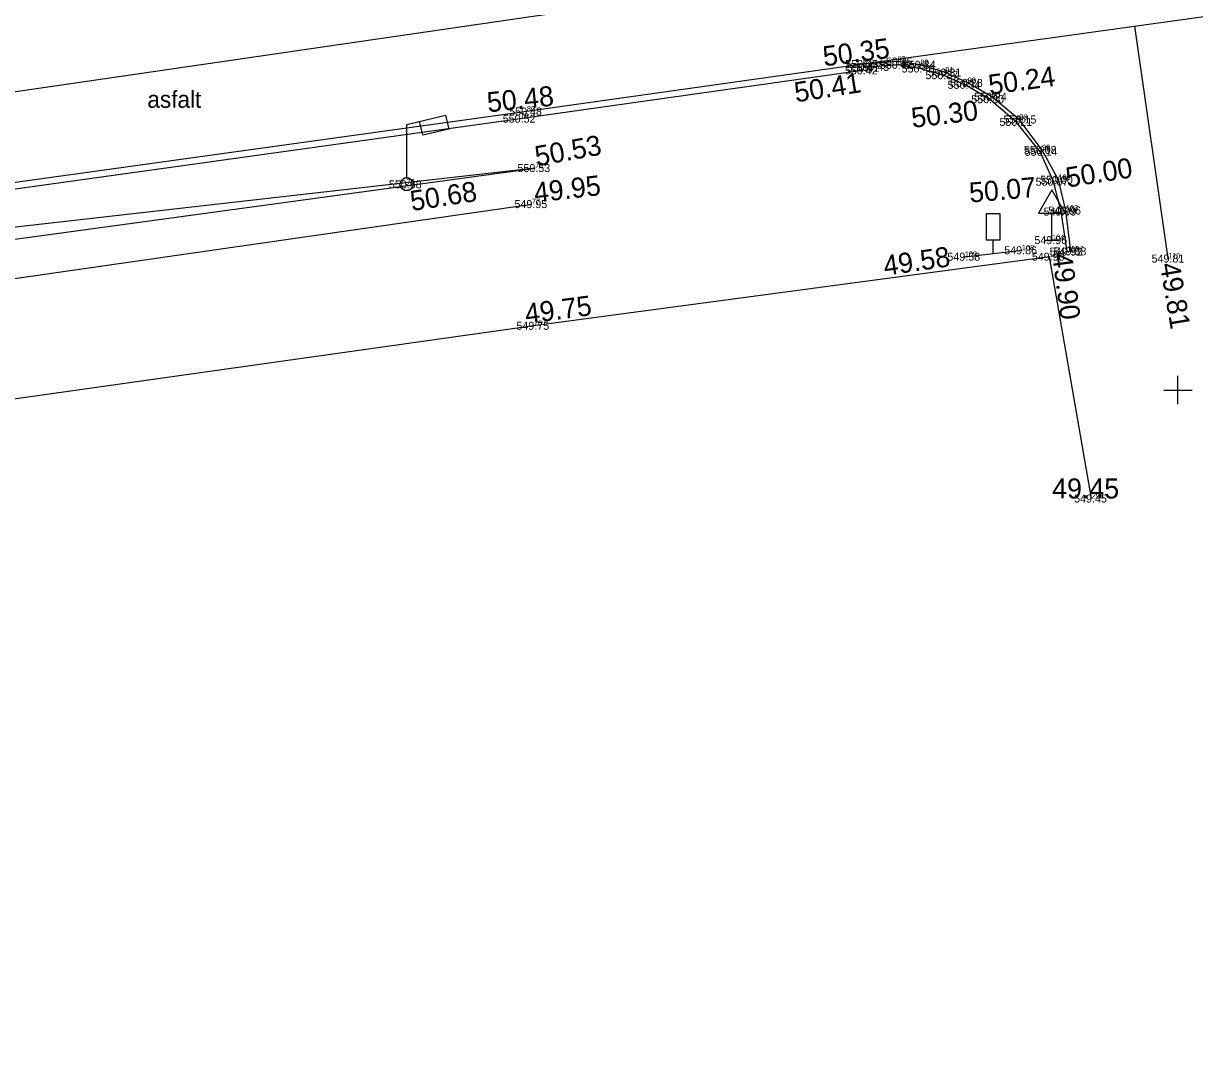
# Model space of a CAD drawing. Extents: x -866693 to -866303, y -1041966 to -1040244.
# Drawn here: x -866593.26 to -866549.38, y -1040325.42 to -1040286.26 of the extents above; entities that cross this region are included whole.
import ezdxf

# ---------------------------------------------------------------- set-up
doc = ezdxf.new("R2010")
doc.units = 0
for name, color, linetype in [('1 hrana zpevněné komunikace-plocha', 7, 'Continuous'), ('10 plot drátěný', 7, 'Continuous'), ('3 osa komunikace', 7, 'Continuous'), ('42 dopravní značka', 7, 'Continuous'), ('43 lampa', 7, 'Continuous'), ('5 obrubník nahoře (chodník)', 7, 'Continuous'), ('7 hrana svah nahoře', 7, 'Continuous'), ('8 hrana svah dole', 7, 'Continuous'), ('82 informační tabule', 7, 'Continuous'), ('Bod', 7, 'Continuous'), ('Nadmořská výška', 7, 'Continuous'), ('Nadmořská výška_tisk', 7, 'Continuous'), ('popisy', 7, 'Continuous'), ('Síť křížek', 7, 'Continuous'), ('Číslo bodu', 7, 'Continuous')]:
    doc.layers.add(name, color=color, linetype=linetype)

msp = doc.modelspace()

# ---------------------------------------------------------------- linework, layer by layer
at = {"layer": '1 hrana zpevněné komunikace-plocha'}
for points in [[(-866503.553, -1040279.722), (-866523.034, -1040282.41), (-866541.374, -1040284.946), (-866561.808, -1040287.782), (-866574.398, -1040289.556), (-866602.398, -1040293.439), (-866619.972, -1040295.863), (-866638.769, -1040298.486), (-866650.196, -1040300.008), (-866657.766, -1040301.183), (-866663.405, -1040303.497), (-866666.7, -1040305.877), (-866670.718, -1040310.555), (-866673.161, -1040315.92), (-866674.075, -1040319.269), (-866673.907, -1040325.701)], [(-866554.01, -1040294.795), (-866554.201, -1040293.268), (-866554.48, -1040292.12), (-866555.095, -1040291.004), (-866555.948, -1040289.861), (-866556.978, -1040289.013), (-866557.879, -1040288.487), (-866558.716, -1040288.097), (-866559.651, -1040287.814), (-866560.506, -1040287.691), (-866561.808, -1040287.782)]]:
    msp.add_lwpolyline(points, dxfattribs=at)
at = {"layer": '10 plot drátěný'}
msp.add_lwpolyline([(-866553.237, -1040304.059), (-866554.808, -1040295.001), (-866574.139, -1040297.591), (-866600.998, -1040301.373), (-866619.297, -1040303.884), (-866638.342, -1040306.448), (-866649.995, -1040308.373)], dxfattribs=at)
at = {"layer": '3 osa komunikace'}
msp.add_line((-866550.37, -1040295.067), (-866551.619, -1040286.368), dxfattribs=at)
msp.add_lwpolyline([(-866675.016, -1040299.403), (-866658.944, -1040297.823), (-866639.253, -1040295.089), (-866620.168, -1040292.742), (-866603.167, -1040290.212), (-866574.251, -1040285.999), (-866539.891, -1040281.121), (-866503.725, -1040276.174)], dxfattribs=at)
at = {"layer": '42 dopravní značka'}
for points in [[(-866554.721, -1040294.375), (-866554.721, -1040293.375), (-866554.221, -1040293.375), (-866554.721, -1040292.5), (-866555.221, -1040293.375), (-866554.721, -1040293.375)], [(-866554.971, -1040294.375), (-866554.471, -1040294.375)]]:
    msp.add_lwpolyline(points, dxfattribs=at)
at = {"layer": '43 lampa'}
for points in [[(-866578.9, -1040292.052), (-866578.825, -1040292.052), (-866578.7, -1040292.142), (-866578.65, -1040292.287), (-866578.7, -1040292.432), (-866578.825, -1040292.522), (-866578.98, -1040292.522), (-866579.105, -1040292.432), (-866579.155, -1040292.287), (-866579.105, -1040292.142), (-866578.98, -1040292.052), (-866578.9, -1040292.052), (-866578.9, -1040290.042), (-866577.45, -1040289.692), (-866577.325, -1040290.217), (-866578.3, -1040290.442), (-866578.425, -1040289.927)], [(-866578.93, -1040292.292), (-866578.87, -1040292.292)]]:
    msp.add_lwpolyline(points, dxfattribs=at)
at = {"layer": '5 obrubník nahoře (chodník)'}
msp.add_lwpolyline([(-866554.158, -1040294.808), (-866554.383, -1040293.311), (-866554.661, -1040292.189), (-866555.162, -1040291.068), (-866556.059, -1040289.95), (-866557.066, -1040289.104), (-866557.969, -1040288.56), (-866558.798, -1040288.2), (-866559.675, -1040287.95), (-866560.507, -1040287.809), (-866561.393, -1040287.885), (-866561.786, -1040287.916), (-866561.819, -1040288.02), (-866574.644, -1040289.831), (-866602.365, -1040293.689)], dxfattribs=at)
at = {"layer": '7 hrana svah nahoře'}
msp.add_line((-866602.083, -1040295.504), (-866574.089, -1040291.683), dxfattribs=at)
msp.add_lwpolyline([(-866574.089, -1040291.683), (-866602.145, -1040294.869), (-866619.361, -1040298.247), (-866637.977, -1040300.426), (-866640.09, -1040300.613)], dxfattribs=at)
at = {"layer": '8 hrana svah dole'}
msp.add_lwpolyline([(-866637.829, -1040301.888), (-866619.387, -1040299.311), (-866601.784, -1040296.996), (-866574.214, -1040293.032)], dxfattribs=at)
at = {"layer": '82 informační tabule'}
msp.add_line((-866557.993, -1040295), (-866555.851, -1040294.759), dxfattribs=at)
msp.add_lwpolyline([(-866556.922, -1040294.88), (-866556.922, -1040294.38), (-866557.172, -1040294.38), (-866557.172, -1040293.38), (-866556.672, -1040293.38), (-866556.672, -1040294.38), (-866556.922, -1040294.38)], dxfattribs=at)
at = {"layer": 'Bod'}
for p, q in [((-866561.808, -1040287.782), (-866561.808, -1040287.782)), ((-866561.786, -1040287.916), (-866561.786, -1040287.916)), ((-866561.393, -1040287.885), (-866561.393, -1040287.885)), ((-866560.507, -1040287.809), (-866560.507, -1040287.809)), ((-866560.506, -1040287.691), (-866560.506, -1040287.691)), ((-866559.651, -1040287.814), (-866559.651, -1040287.814)), ((-866561.819, -1040288.02), (-866561.819, -1040288.02)), ((-866559.675, -1040287.95), (-866559.675, -1040287.95)), ((-866558.798, -1040288.2), (-866558.798, -1040288.2)), ((-866558.716, -1040288.097), (-866558.716, -1040288.097)), ((-866557.969, -1040288.56), (-866557.969, -1040288.56)), ((-866557.879, -1040288.487), (-866557.879, -1040288.487)), ((-866557.066, -1040289.104), (-866557.066, -1040289.104)), ((-866556.978, -1040289.013), (-866556.978, -1040289.013)), ((-866574.398, -1040289.556), (-866574.398, -1040289.556)), ((-866574.644, -1040289.831), (-866574.644, -1040289.831)), ((-866556.059, -1040289.95), (-866556.059, -1040289.95)), ((-866555.948, -1040289.861), (-866555.948, -1040289.861)), ((-866555.162, -1040291.068), (-866555.162, -1040291.068)), ((-866555.095, -1040291.004), (-866555.095, -1040291.004)), ((-866574.089, -1040291.683), (-866574.089, -1040291.683)), ((-866578.9, -1040292.292), (-866578.9, -1040292.292)), ((-866554.661, -1040292.189), (-866554.661, -1040292.189)), ((-866554.48, -1040292.12), (-866554.48, -1040292.12)), ((-866574.214, -1040293.032), (-866574.214, -1040293.032)), ((-866554.383, -1040293.311), (-866554.383, -1040293.311)), ((-866554.201, -1040293.268), (-866554.201, -1040293.268)), ((-866554.721, -1040294.375), (-866554.721, -1040294.375)), ((-866555.851, -1040294.759), (-866555.851, -1040294.759)), ((-866554.158, -1040294.808), (-866554.158, -1040294.808)), ((-866554.01, -1040294.795), (-866554.01, -1040294.795)), ((-866557.993, -1040295), (-866557.993, -1040295)), ((-866554.808, -1040295.001), (-866554.808, -1040295.001)), ((-866550.37, -1040295.067), (-866550.37, -1040295.067)), ((-866574.139, -1040297.591), (-866574.139, -1040297.591)), ((-866553.237, -1040304.059), (-866553.237, -1040304.059))]:
    msp.add_line(p, q, dxfattribs=at)
at = {"layer": 'Síť křížek'}
for p, q in [((-866550, -1040300.53), (-866550, -1040299.47)), ((-866550.53, -1040300), (-866549.47, -1040300))]:
    msp.add_line(p, q, dxfattribs=at)

# ---------------------------------------------------------------- texts
at = {"layer": 'Nadmořská výška'}
for s, p in [('550.42', (-866562.482, -1040288.17)), ('550.35', (-866562.472, -1040287.93)), ('550.41', (-866562.419, -1040288.07)), ('550.43', (-866562.052, -1040288.04)), ('550.35', (-866561.172, -1040287.84)), ('550.42', (-866561.172, -1040287.96)), ('550.40', (-866560.355, -1040288.1)), ('550.34', (-866560.312, -1040287.96)), ('550.37', (-866559.462, -1040288.35)), ('550.31', (-866559.349, -1040288.25)), ('550.28', (-866558.542, -1040288.64)), ('550.34', (-866558.632, -1040288.71)), ('550.30', (-866557.745, -1040289.25)), ('550.24', (-866557.642, -1040289.16)), ('550.52', (-866575.302, -1040289.98)), ('550.48', (-866575.062, -1040289.71)), ('550.21', (-866556.689, -1040290.1)), ('550.15', (-866556.533, -1040290.01)), ('550.08', (-866555.775, -1040291.15)), ('550.14', (-866555.743, -1040291.22)), ('550.53', (-866574.752, -1040291.83)), ('550.68', (-866579.57, -1040292.44)), ('550.07', (-866555.335, -1040292.34)), ('550.00', (-866555.167, -1040292.27)), ('549.95', (-866574.863, -1040293.18)), ('549.99', (-866555.034, -1040293.46)), ('549.96', (-866554.86, -1040293.42)), ('549.96', (-866555.38, -1040294.53)), ('549.58', (-866558.641, -1040295.15)), ('549.86', (-866556.509, -1040294.91)), ('549.90', (-866555.475, -1040295.15)), ('549.92', (-866554.813, -1040294.96)), ('549.88', (-866554.661, -1040294.95)), ('549.81', (-866550.988, -1040295.22)), ('549.75', (-866574.791, -1040297.74)), ('549.45', (-866553.891, -1040304.21))]:
    msp.add_text(s, height=0.3, dxfattribs=at).set_placement(p)
at = {"layer": 'Nadmořská výška_tisk'}
for s, rotation, p in [('50.35', 7.4587, (-866563.256, -1040287.872)), ('50.24', 7.7628, (-866557.051, -1040288.937)), ('50.41', 8.8499, (-866564.315, -1040289.22)), ('50.48', 5.7729, (-866575.856, -1040289.592)), ('50.30', 6.8127, (-866559.949, -1040290.175)), ('50.53', 10.2506, (-866574.026, -1040291.615)), ('50.00', 8.8961, (-866554.143, -1040292.412)), ('50.68', 8.7463, (-866578.711, -1040293.29)), ('49.95', 6.674, (-866574.089, -1040292.978)), ('50.07', 5.0135, (-866557.793, -1040292.977)), ('49.58', 8.2752, (-866560.982, -1040295.715)), ('49.90', 277.5042, (-866554.718, -1040294.913)), ('49.81', 279.5117, (-866550.68, -1040295.281)), ('49.75', 7.4661, (-866574.423, -1040297.515))]:
    msp.add_text(s, height=0.75, rotation=rotation, dxfattribs=at).set_placement(p)
msp.add_text('49.45', height=0.75, dxfattribs=at).set_placement((-866554.714, -1040304.059))
at = {"layer": 'popisy'}
msp.add_text('asfalt', height=0.632, dxfattribs=at).set_placement((-866588.62, -1040289.422))
at = {"layer": 'Číslo bodu'}
for s, p in [('87', (-866560.506, -1040287.691)), ('83', (-866561.819, -1040288.02)), ('82', (-866561.808, -1040287.782)), ('84', (-866561.786, -1040287.916)), ('85', (-866561.393, -1040287.885)), ('86', (-866560.507, -1040287.809)), ('89', (-866559.675, -1040287.95)), ('88', (-866559.651, -1040287.814)), ('91', (-866558.716, -1040288.097)), ('90', (-866558.798, -1040288.2)), ('93', (-866557.969, -1040288.56)), ('92', (-866557.879, -1040288.487)), ('94', (-866557.066, -1040289.104)), ('95', (-866556.978, -1040289.013)), ('79', (-866574.644, -1040289.831)), ('80', (-866574.398, -1040289.556)), ('96', (-866555.948, -1040289.861)), ('97', (-866556.059, -1040289.95)), ('98', (-866555.162, -1040291.068)), ('99', (-866555.095, -1040291.004)), ('78', (-866574.089, -1040291.683)), ('75', (-866578.9, -1040292.292)), ('101', (-866554.661, -1040292.189)), ('100', (-866554.48, -1040292.12)), ('77', (-866574.214, -1040293.032)), ('102', (-866554.383, -1040293.311)), ('103', (-866554.201, -1040293.268)), ('104', (-866554.721, -1040294.375)), ('109', (-866557.993, -1040295)), ('108', (-866555.851, -1040294.759)), ('105', (-866554.808, -1040295.001)), ('106', (-866554.158, -1040294.808)), ('107', (-866554.01, -1040294.795)), ('110', (-866550.37, -1040295.067)), ('76', (-866574.139, -1040297.591)), ('294', (-866553.237, -1040304.059))]:
    msp.add_text(s, height=0.2, dxfattribs=at).set_placement(p)

doc.saveas('drawing.dxf')
